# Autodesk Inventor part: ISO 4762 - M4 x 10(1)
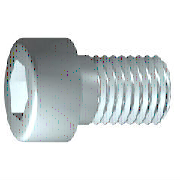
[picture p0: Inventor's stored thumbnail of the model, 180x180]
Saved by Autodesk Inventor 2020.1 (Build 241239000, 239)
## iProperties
Created: 2019-01
Part Number: ISO 4762 - M4 x 10(1)
Material: Edelstahl, 440C
Description: Innensechskantschraube
Document SubType Name: Modeling
Standard: ISO 4762
Designer: lutzd
Standard Revision: Fourth edition 2004-03-01
Standards Organization: ISO
Language: de-DE
Size Designation: M4 x 10
Categories: <MemberInstance><Categories><Category DisplayName="Verbindungselemente" InternalName="e4da775c-781d-43d5-af7c-5136215cf5a6" Mnemonic="FSTN"><Category DisplayNam
Mass: 2.0086 g
Surface Area: 3.0572 cm^2
Volume: 0.259174 cm^3
Density: 7.75 g/cm^3
Appearance: Halbpoliert
IsCustomPart: 0
Author: lutzd
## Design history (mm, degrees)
workplane "Work Plane1"
fillet "Fillet2" dims "d30" = 0.1 (= R)
sketch "Skizze1"
  geometry: L1 (-1, 0)-(10, 0); L2 (10, 0)-(10, 2); L3 (10, 2)-(1.75, 2); L4 (1.75, 2)-(1.32, 2); L5 (1.32, 2)-(0, 2); L6 (0, 2)-(0, 3.5); L7 (0, 3.5)-(-4, 3.5); L8 (-4, 3.5)-(-4, 1.732); L9 (-4, 1.732)-(-2, 1.732); L10 (-2, 1.732)-(-1, 0); L11 (-6.8, 0)-(12.8, 0) reference; L12 (0, -0.7)-(0, 4.2) reference; L13 (1.75, 2)-(0, 2)
  constraints: 22 end point, 6 parallel, 2 collinear, 2 perpendicular, 1 horizontal, 1 point on line
  dimensions: "d1" = 8.25 distance from line of L3.end L2 (= GEL); "d2" = 0.42952 distance of L4.end L3.end (computed from GAL); "d3" = 4 distance between parallel lines of L8 L6 (= KOH); "d4" = 2 distance of L8.end L9.end (= INTI); "d5" = 60 deg angle of L10 L1; "d6" = 4 diameter of L3 L1 (= GD); "d7" = 4 diameter of L5 L1 (= BDM); "d8" = 3.4641 diameter of L9 L1 (= 1.1547 x SW); "d9" = 7 diameter of L7 L1 (= KOD); "d26" = 10 distance between parallel lines of L12 L2 (= NLG)
revolve "Körper" sketch "Skizze1" stored, may be unused: angle "d10" = 90 deg
sketch "Skizze2"
  geometry: L1 (0, -4.9)-(0, 4.9) reference; L2 (-4.9, 0)-(4.9, 0) reference; L3 (1.732, 0)-(0.866, -1.5); L4 (0.866, -1.5)-(-0.866, -1.5); L5 (-0.866, -1.5)-(-1.732, 0); L6 (-1.732, 0)-(-0.866, 1.5); L7 (-0.866, 1.5)-(0.866, 1.5); L8 (0.866, 1.5)-(1.732, 0); 2 further points
  constraints: 12 end point, 1 coincident, 1 horizontal alignment, 1 point on line, 12 other
extrude "Loch" join sketch "Skizze2" stored distance "d11" = 10; taper "d12" = 0 deg
body "Solid1"
fillet "Rundung1" dims "d17" = 0.4 (= RR)
feature "Gewinde" dims "d13" = 8.25 (= GEL), "d14" = 0
chamfer "Fase1" distance "d15" = 0.42941 (= -0.5 x SPD + 0.5 x GD); stored, may be unused: second distance "d16" = 0.42941 (= GUL), angle "d27" = 45 deg
other parameters: "GD" = 4 [user parameter; used in 2 equation terms], "NLG" = 10 [user parameter; used in 1 equation term], "GEL" = 8.25 [user parameter; used in 2 equation terms], "KOD" = 7 [user parameter; used in 1 equation term], "KOH" = 4 [user parameter; used in 1 equation term], "INTI" = 2 [user parameter; used in 1 equation term], "GAL" = 0.42941 (= 0.61345 x PTC) [user parameter; used in 1 equation term], "GUL" = 0.42941 (= 0.61345 x PTC) [user parameter; used in 1 equation term], "BDM" = 4 (= NND) [user parameter; used in 1 equation term], "SW" = 3 [user parameter; used in 2 equation terms], "RR" = 0.4 [user parameter; used in 1 equation term], "SPD" = 3.14117 (= NND - 1.2269 x PTC) [user parameter; used in 1 equation term], "d19" = 0, "d28" = 0, "d29" = 0, "R" = 0.1 [user parameter; used in 1 equation term], "TOA" = 30 deg [user parameter], "GD1" = 3.14117 (= THREADDIA - 1.2269 x PTC) [user parameter], "THREADDIA" = 4 [user parameter; used in 1 equation term], "FAWI" = 45 deg [user parameter], "TPU" = 14.28571 (computed from PTC) [user parameter], "PTC" = 0.7 [user parameter; used in 5 equation terms], "NND" = 4 [user parameter; used in 2 equation terms], "E0" = 3.465 (= 1.155 x SW) [user parameter]
